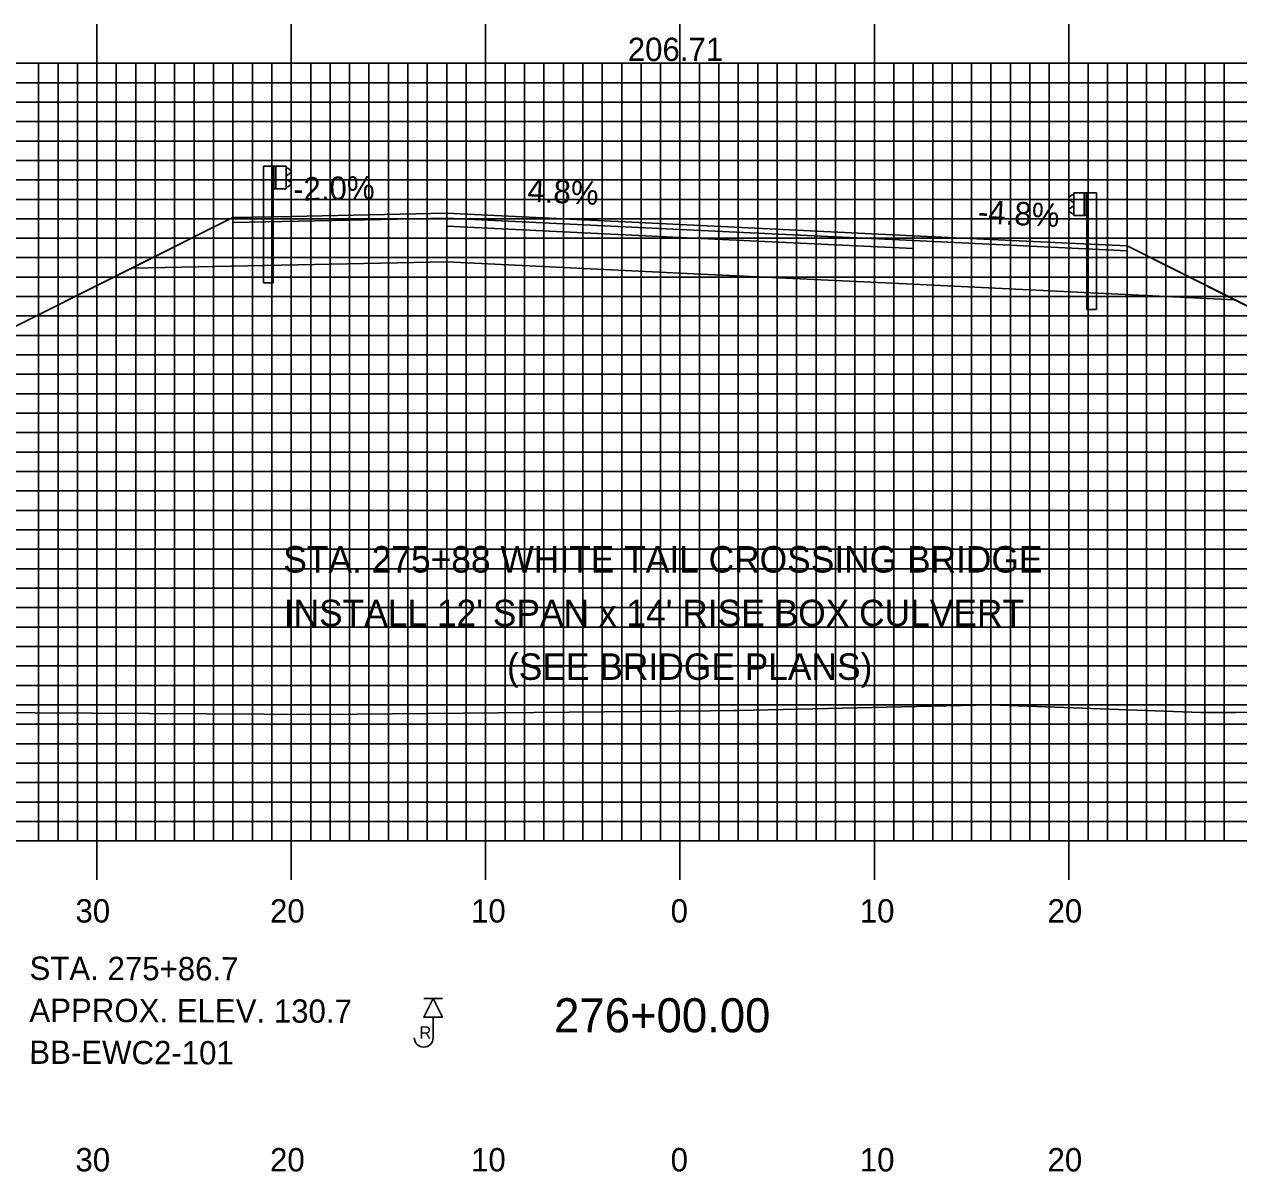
# Model space of a CAD drawing. Extents: x 1809800 to 1810143, y 442591 to 442811.
# Drawn here: x 1809931.6 to 1809994.1, y 442656.6 to 442715.7 of the extents above; entities that cross this region are included whole.
import ezdxf

# ---------------------------------------------------------------- set-up
doc = ezdxf.new("R2010")
doc.units = 0
for name, color, linetype in [('ANNOTATION', 7, 'Continuous'), ('BORING - REFUSAL', 7, 'Continuous'), ('D_Guardrail_Beam_Lt', 7, 'Continuous'), ('D_Guardrail_Beam_Rt', 7, 'Continuous'), ('D_Roadway_Centerline', 7, 'Continuous'), ('D_Roadway_Centerline_Text', 7, 'Continuous'), ('D_Roadway_Edge_Shoulder', 7, 'Continuous'), ('D_Roadway_Edge_TW', 7, 'Continuous'), ('D_Roadway_Pavement', 7, 'Continuous'), ('D_Roadway_SlopeLines', 7, 'Continuous'), ('D_Roadway_SubGrade', 7, 'Continuous'), ('H_V ANNOTATION', 7, 'Continuous'), ('MAJOR', 7, 'Continuous'), ('MINOR', 7, 'Continuous'), ('S_Roadway_Centerline', 7, 'Continuous')]:
    doc.layers.add(name, color=color, linetype=linetype)

msp = doc.modelspace()

# ---------------------------------------------------------------- linework, layer by layer
at = {"layer": 'BORING - REFUSAL'}
for p, q in [((1809953.13, 442665.558), (1809952.171, 442665.558)), ((1809952.65, 442664.598), (1809952.65, 442663.539))]:
    msp.add_line(p, q, dxfattribs=at)
msp.add_lwpolyline([(1809952.65, 442665.558), (1809953.13, 442664.598), (1809952.171, 442664.598)], close=True, dxfattribs=at)
msp.add_arc((1809952.165, 442663.539), 0.485, 180, 0, dxfattribs=at)
at = {"layer": 'D_Guardrail_Beam_Lt'}
for p, q in [((1809943.921, 442708.37), (1809943.921, 442702.37)), ((1809944.392, 442708.37), (1809943.921, 442708.37)), ((1809945.08, 442708.37), (1809944.392, 442708.37)), ((1809944.392, 442708.37), (1809944.392, 442707.203)), ((1809944.455, 442708.37), (1809944.455, 442707.203)), ((1809944.559, 442708.37), (1809944.559, 442707.203)), ((1809945.08, 442707.203), (1809945.08, 442708.37)), ((1809945.08, 442708.286), (1809945.154, 442708.272)), ((1809945.084, 442707.821), (1809945.084, 442707.751)), ((1809945.313, 442708.022), (1809945.118, 442707.886)), ((1809945.17, 442708.265), (1809945.313, 442708.165)), ((1809944.392, 442707.203), (1809945.08, 442707.203)), ((1809944.413, 442702.37), (1809944.413, 442707.203)), ((1809945.154, 442707.301), (1809945.08, 442707.286)), ((1809945.118, 442707.687), (1809945.313, 442707.551)), ((1809945.313, 442707.407), (1809945.17, 442707.307)), ((1809944.413, 442702.37), (1809943.921, 442702.37))]:
    msp.add_line(p, q, dxfattribs=at)
for centre, major_axis, start_param, end_param in [((1809945.163, 442707.821), (-0.0789, 0), 5.323254, 6.283185), ((1809945.163, 442707.751), (-0.0789, 0), 6.283185, 7.243116), ((1809945.146, 442708.231), (0.0417, 0), 0.959931, 1.376053), ((1809945.263, 442708.093), (0.0877, 0), 5.323254, 7.243116), ((1809945.146, 442707.341), (0.0417, 0), 4.907132, 5.323254), ((1809945.263, 442707.479), (0.0877, 0), 5.323254, 7.243116)]:
    msp.add_ellipse(centre, major_axis=major_axis, ratio=0.995501, start_param=start_param, end_param=end_param, dxfattribs=at)
at = {"layer": 'D_Guardrail_Beam_Rt'}
for p, q in [((1809985.531, 442706.889), (1809985.388, 442706.789)), ((1809985.388, 442706.646), (1809985.583, 442706.51)), ((1809985.621, 442706.91), (1809985.547, 442706.896)), ((1809985.621, 442706.994), (1809986.309, 442706.994)), ((1809985.621, 442705.827), (1809985.621, 442706.994)), ((1809986.142, 442706.994), (1809986.142, 442705.827)), ((1809986.246, 442706.994), (1809986.246, 442705.827)), ((1809986.309, 442706.994), (1809986.78, 442706.994)), ((1809986.309, 442706.994), (1809986.309, 442705.827)), ((1809986.78, 442706.994), (1809986.78, 442700.994)), ((1809985.583, 442706.311), (1809985.388, 442706.175)), ((1809985.388, 442706.031), (1809985.531, 442705.931)), ((1809985.547, 442705.925), (1809985.621, 442705.91)), ((1809985.617, 442706.445), (1809985.617, 442706.375)), ((1809986.309, 442705.827), (1809985.621, 442705.827)), ((1809986.288, 442700.994), (1809986.288, 442705.827)), ((1809986.288, 442700.994), (1809986.78, 442700.994))]:
    msp.add_line(p, q, dxfattribs=at)
for centre, major_axis, start_param, end_param in [((1809985.438, 442706.717), (-0.0877, 0), 5.323254, 7.243116), ((1809985.555, 442706.855), (-0.0417, 0), 4.907132, 5.323254), ((1809985.538, 442706.445), (0.0789, 0), 0, 0.959931), ((1809985.438, 442706.103), (-0.0877, 0), 5.323254, 7.243116), ((1809985.555, 442705.965), (-0.0417, 0), 0.959931, 1.376053), ((1809985.538, 442706.375), (0.0789, 0), 5.323254, 6.283185)]:
    msp.add_ellipse(centre, major_axis=major_axis, ratio=0.995501, start_param=start_param, end_param=end_param, dxfattribs=at)
at = {"layer": 'D_Roadway_Centerline'}
msp.add_lwpolyline([(1809890.342, 442679.722), (1809937.142, 442703.122), (1809942.35, 442705.726), (1809945.35, 442705.786), (1809953.35, 442705.946), (1809965.35, 442705.37), (1809977.35, 442704.794), (1809985.35, 442704.41), (1809988.35, 442704.266), (1809993.881, 442701.501), (1810036.244, 442680.319)], dxfattribs=at)
at = {"layer": 'D_Roadway_Edge_Shoulder'}
for points in [[(1809953.35, 442705.946), (1809945.35, 442705.786), (1809945.35, 442705.786), (1809942.35, 442705.726), (1809942.35, 442705.476), (1809953.35, 442705.696)], [(1809977.35, 442704.794), (1809985.35, 442704.41), (1809985.35, 442704.41), (1809988.35, 442704.266), (1809988.35, 442704.016), (1809977.35, 442704.544)]]:
    msp.add_lwpolyline(points, close=True, dxfattribs=at)
at = {"layer": 'D_Roadway_Edge_TW'}
msp.add_lwpolyline([(1809953.35, 442705.696), (1809953.35, 442705.946), (1809965.35, 442705.37), (1809977.35, 442704.794), (1809977.35, 442704.544), (1809965.35, 442705.12)], close=True, dxfattribs=at)
at = {"layer": 'D_Roadway_Pavement'}
msp.add_lwpolyline([(1809953.35, 442705.28), (1809953.35, 442705.696), (1809965.35, 442705.12), (1809977.35, 442704.544), (1809977.35, 442704.128), (1809965.35, 442704.704)], close=True, dxfattribs=at)
for points in [[(1809953.35, 442705.696), (1809953.35, 442705.28)], [(1809977.35, 442704.544), (1809977.35, 442704.128)]]:
    msp.add_lwpolyline(points, dxfattribs=at)
at = {"layer": 'D_Roadway_SlopeLines'}
for points in [[(1809942.35, 442705.726), (1809890.342, 442679.722)], [(1809988.35, 442704.266), (1810036.244, 442680.319)]]:
    msp.add_lwpolyline(points, dxfattribs=at)
at = {"layer": 'D_Roadway_SubGrade'}
for points in [[(1809953.35, 442705.28), (1809953.35, 442705.696), (1809942.35, 442705.476), (1809942.35, 442705.726), (1809937.142, 442703.122), (1809953.35, 442703.446)], [(1809953.35, 442703.446), (1809953.35, 442705.696), (1809953.35, 442705.28), (1809965.35, 442704.704), (1809977.35, 442704.128), (1809977.35, 442704.544), (1809977.35, 442702.294), (1809965.35, 442702.87)], [(1809977.35, 442704.128), (1809977.35, 442704.544), (1809988.35, 442704.016), (1809988.35, 442704.266), (1809993.881, 442701.501), (1809977.35, 442702.294)]]:
    msp.add_lwpolyline(points, close=True, dxfattribs=at)
at = {"layer": 'MAJOR'}
for p, q in [((1809935.35, 442715.669), (1809935.35, 442713.665)), ((1809945.35, 442715.669), (1809945.35, 442713.665)), ((1809955.35, 442715.669), (1809955.35, 442713.665)), ((1809965.35, 442715.669), (1809965.35, 442713.665)), ((1809975.35, 442715.669), (1809975.35, 442713.665)), ((1809985.35, 442715.669), (1809985.35, 442713.665)), ((1809825.35, 442713.665), (1810105.35, 442713.665)), ((1809825.35, 442713.665), (1810105.35, 442713.665)), ((1809935.35, 442673.665), (1809935.35, 442713.665)), ((1809945.35, 442673.665), (1809945.35, 442713.665)), ((1809955.35, 442673.665), (1809955.35, 442713.665)), ((1809965.35, 442673.665), (1809965.35, 442713.665)), ((1809975.35, 442673.665), (1809975.35, 442713.665)), ((1809985.35, 442673.665), (1809985.35, 442713.665)), ((1809825.35, 442708.665), (1810105.35, 442708.665)), ((1809825.35, 442703.665), (1810105.35, 442703.665)), ((1809825.35, 442698.665), (1810105.35, 442698.665)), ((1809825.35, 442693.665), (1810105.35, 442693.665)), ((1809825.35, 442688.665), (1810105.35, 442688.665)), ((1809825.35, 442683.665), (1810105.35, 442683.665)), ((1809825.35, 442678.665), (1810105.35, 442678.665)), ((1809825.35, 442673.665), (1810105.35, 442673.665)), ((1809825.35, 442673.665), (1810105.35, 442673.665)), ((1809935.35, 442671.661), (1809935.35, 442673.665)), ((1809945.35, 442671.661), (1809945.35, 442673.665)), ((1809955.35, 442671.661), (1809955.35, 442673.665)), ((1809965.35, 442671.661), (1809965.35, 442673.665)), ((1809975.35, 442671.661), (1809975.35, 442673.665)), ((1809985.35, 442671.661), (1809985.35, 442673.665))]:
    msp.add_line(p, q, dxfattribs=at)
at = {"layer": 'MINOR'}
for p, q in [((1809932.35, 442673.665), (1809932.35, 442713.665)), ((1809933.35, 442673.665), (1809933.35, 442713.665)), ((1809934.35, 442673.665), (1809934.35, 442713.665)), ((1809936.35, 442673.665), (1809936.35, 442713.665)), ((1809937.35, 442673.665), (1809937.35, 442713.665)), ((1809938.35, 442673.665), (1809938.35, 442713.665)), ((1809939.35, 442673.665), (1809939.35, 442713.665)), ((1809940.35, 442673.665), (1809940.35, 442713.665)), ((1809941.35, 442673.665), (1809941.35, 442713.665)), ((1809942.35, 442673.665), (1809942.35, 442713.665)), ((1809943.35, 442673.665), (1809943.35, 442713.665)), ((1809944.35, 442673.665), (1809944.35, 442713.665)), ((1809946.35, 442673.665), (1809946.35, 442713.665)), ((1809947.35, 442673.665), (1809947.35, 442713.665)), ((1809948.35, 442673.665), (1809948.35, 442713.665)), ((1809949.35, 442673.665), (1809949.35, 442713.665)), ((1809950.35, 442673.665), (1809950.35, 442713.665)), ((1809951.35, 442673.665), (1809951.35, 442713.665)), ((1809952.35, 442673.665), (1809952.35, 442713.665)), ((1809953.35, 442673.665), (1809953.35, 442713.665)), ((1809954.35, 442673.665), (1809954.35, 442713.665)), ((1809956.35, 442673.665), (1809956.35, 442713.665)), ((1809957.35, 442673.665), (1809957.35, 442713.665)), ((1809958.35, 442673.665), (1809958.35, 442713.665)), ((1809959.35, 442673.665), (1809959.35, 442713.665)), ((1809960.35, 442673.665), (1809960.35, 442713.665)), ((1809961.35, 442673.665), (1809961.35, 442713.665)), ((1809962.35, 442673.665), (1809962.35, 442713.665)), ((1809963.35, 442673.665), (1809963.35, 442713.665)), ((1809964.35, 442673.665), (1809964.35, 442713.665)), ((1809966.35, 442673.665), (1809966.35, 442713.665)), ((1809967.35, 442673.665), (1809967.35, 442713.665)), ((1809968.35, 442673.665), (1809968.35, 442713.665)), ((1809969.35, 442673.665), (1809969.35, 442713.665)), ((1809970.35, 442673.665), (1809970.35, 442713.665)), ((1809971.35, 442673.665), (1809971.35, 442713.665)), ((1809972.35, 442673.665), (1809972.35, 442713.665)), ((1809973.35, 442673.665), (1809973.35, 442713.665)), ((1809974.35, 442673.665), (1809974.35, 442713.665)), ((1809976.35, 442673.665), (1809976.35, 442713.665)), ((1809977.35, 442673.665), (1809977.35, 442713.665)), ((1809978.35, 442673.665), (1809978.35, 442713.665)), ((1809979.35, 442673.665), (1809979.35, 442713.665)), ((1809980.35, 442673.665), (1809980.35, 442713.665)), ((1809981.35, 442673.665), (1809981.35, 442713.665)), ((1809982.35, 442673.665), (1809982.35, 442713.665)), ((1809983.35, 442673.665), (1809983.35, 442713.665)), ((1809984.35, 442673.665), (1809984.35, 442713.665)), ((1809986.35, 442673.665), (1809986.35, 442713.665)), ((1809987.35, 442673.665), (1809987.35, 442713.665)), ((1809988.35, 442673.665), (1809988.35, 442713.665)), ((1809989.35, 442673.665), (1809989.35, 442713.665)), ((1809990.35, 442673.665), (1809990.35, 442713.665)), ((1809991.35, 442673.665), (1809991.35, 442713.665)), ((1809992.35, 442673.665), (1809992.35, 442713.665)), ((1809993.35, 442673.665), (1809993.35, 442713.665)), ((1809825.35, 442712.665), (1810105.35, 442712.665)), ((1809825.35, 442711.665), (1810105.35, 442711.665)), ((1809825.35, 442710.665), (1810105.35, 442710.665)), ((1809825.35, 442709.665), (1810105.35, 442709.665)), ((1809825.35, 442707.665), (1810105.35, 442707.665)), ((1809825.35, 442706.665), (1810105.35, 442706.665)), ((1809825.35, 442705.665), (1810105.35, 442705.665)), ((1809825.35, 442704.665), (1810105.35, 442704.665)), ((1809825.35, 442702.665), (1810105.35, 442702.665)), ((1809825.35, 442701.665), (1810105.35, 442701.665)), ((1809825.35, 442700.665), (1810105.35, 442700.665)), ((1809825.35, 442699.665), (1810105.35, 442699.665)), ((1809825.35, 442697.665), (1810105.35, 442697.665)), ((1809825.35, 442696.665), (1810105.35, 442696.665)), ((1809825.35, 442695.665), (1810105.35, 442695.665)), ((1809825.35, 442694.665), (1810105.35, 442694.665)), ((1809825.35, 442692.665), (1810105.35, 442692.665)), ((1809825.35, 442691.665), (1810105.35, 442691.665)), ((1809825.35, 442690.665), (1810105.35, 442690.665)), ((1809825.35, 442689.665), (1810105.35, 442689.665)), ((1809825.35, 442687.665), (1810105.35, 442687.665)), ((1809825.35, 442686.665), (1810105.35, 442686.665)), ((1809825.35, 442685.665), (1810105.35, 442685.665)), ((1809825.35, 442684.665), (1810105.35, 442684.665)), ((1809825.35, 442682.665), (1810105.35, 442682.665)), ((1809825.35, 442681.665), (1810105.35, 442681.665)), ((1809825.35, 442680.665), (1810105.35, 442680.665)), ((1809825.35, 442679.665), (1810105.35, 442679.665)), ((1809825.35, 442677.665), (1810105.35, 442677.665)), ((1809825.35, 442676.665), (1810105.35, 442676.665)), ((1809825.35, 442675.665), (1810105.35, 442675.665)), ((1809825.35, 442674.665), (1810105.35, 442674.665))]:
    msp.add_line(p, q, dxfattribs=at)
at = {"layer": 'S_Roadway_Centerline'}
msp.add_lwpolyline([(1809825.35, 442679.697), (1809828.049, 442679.759), (1809855.593, 442679.798), (1809880.691, 442679.707), (1809893.543, 442679.727), (1809898.831, 442679.945), (1809917.983, 442680.221), (1809923.047, 442680.389), (1809926.253, 442680.285), (1809946.904, 442680.158), (1809966.915, 442680.356), (1809968.111, 442680.367), (1809968.217, 442680.367), (1809968.353, 442680.37), (1809981.342, 442680.669), (1809992.142, 442680.277), (1809993.934, 442680.261), (1810003.994, 442680.434)], dxfattribs=at)

# ---------------------------------------------------------------- texts
at = {"layer": 'ANNOTATION'}
for s, rotation, p in [('-2.0%', 1.14576, (1809945.457, 442706.589)), ('4.8%', 357.25191, (1809957.48, 442706.55)), ('-4.8%', 357.25191, (1809980.659, 442705.438))]:
    msp.add_text(s, height=1.2, rotation=rotation, dxfattribs=at).set_placement(p)
for s, p in [('STA. 275+88 WHITE TAIL CROSSING BRIDGE', (1809944.94, 442687.468)), ("INSTALL 12' SPAN x 14' RISE BOX CULVERT", (1809944.962, 442684.708)), ('(SEE BRIDGE PLANS)', (1809956.45, 442681.948))]:
    msp.add_text(s, height=1.36, dxfattribs=at).set_placement(p)
at = {"layer": 'BORING - REFUSAL'}
for s, p in [('STA. 275+86.7', (1809931.884, 442666.517)), ('APPROX. ELEV. 130.7', (1809931.877, 442664.357)), ('BB-EWC2-101', (1809931.87, 442662.197))]:
    msp.add_text(s, height=1.2, rotation=359.81416, dxfattribs=at).set_placement(p)
msp.add_text('R', height=0.64, dxfattribs=at).set_placement((1809951.941, 442663.483))
at = {"layer": 'D_Roadway_Centerline'}
for s, p in [('C', (1809965.345, 442705.37)), ('L', (1809965.35, 442705.363))]:
    msp.add_text(s, height=0.0146, dxfattribs=at).set_placement(p)
at = {"layer": 'D_Roadway_Centerline_Text'}
msp.add_text('206.71', height=1.2, dxfattribs=at).set_placement((1809962.664, 442713.78))
at = {"layer": 'H_V ANNOTATION'}
for s, height, p in [('30', 1.2, (1809934.248, 442669.465)), ('20', 1.2, (1809944.258, 442669.465)), ('10', 1.2, (1809954.601, 442669.465)), ('0', 1.2, (1809964.869, 442669.465)), ('10', 1.2, (1809974.601, 442669.465)), ('20', 1.2, (1809984.258, 442669.465)), ('276+00.00', 1.75, (1809958.874, 442663.821)), ('30', 1.2, (1809934.248, 442656.665)), ('20', 1.2, (1809944.258, 442656.665)), ('10', 1.2, (1809954.601, 442656.665)), ('0', 1.2, (1809964.869, 442656.665)), ('10', 1.2, (1809974.601, 442656.665)), ('20', 1.2, (1809984.258, 442656.665))]:
    msp.add_text(s, height=height, dxfattribs=at).set_placement(p)

doc.saveas('drawing.dxf')
